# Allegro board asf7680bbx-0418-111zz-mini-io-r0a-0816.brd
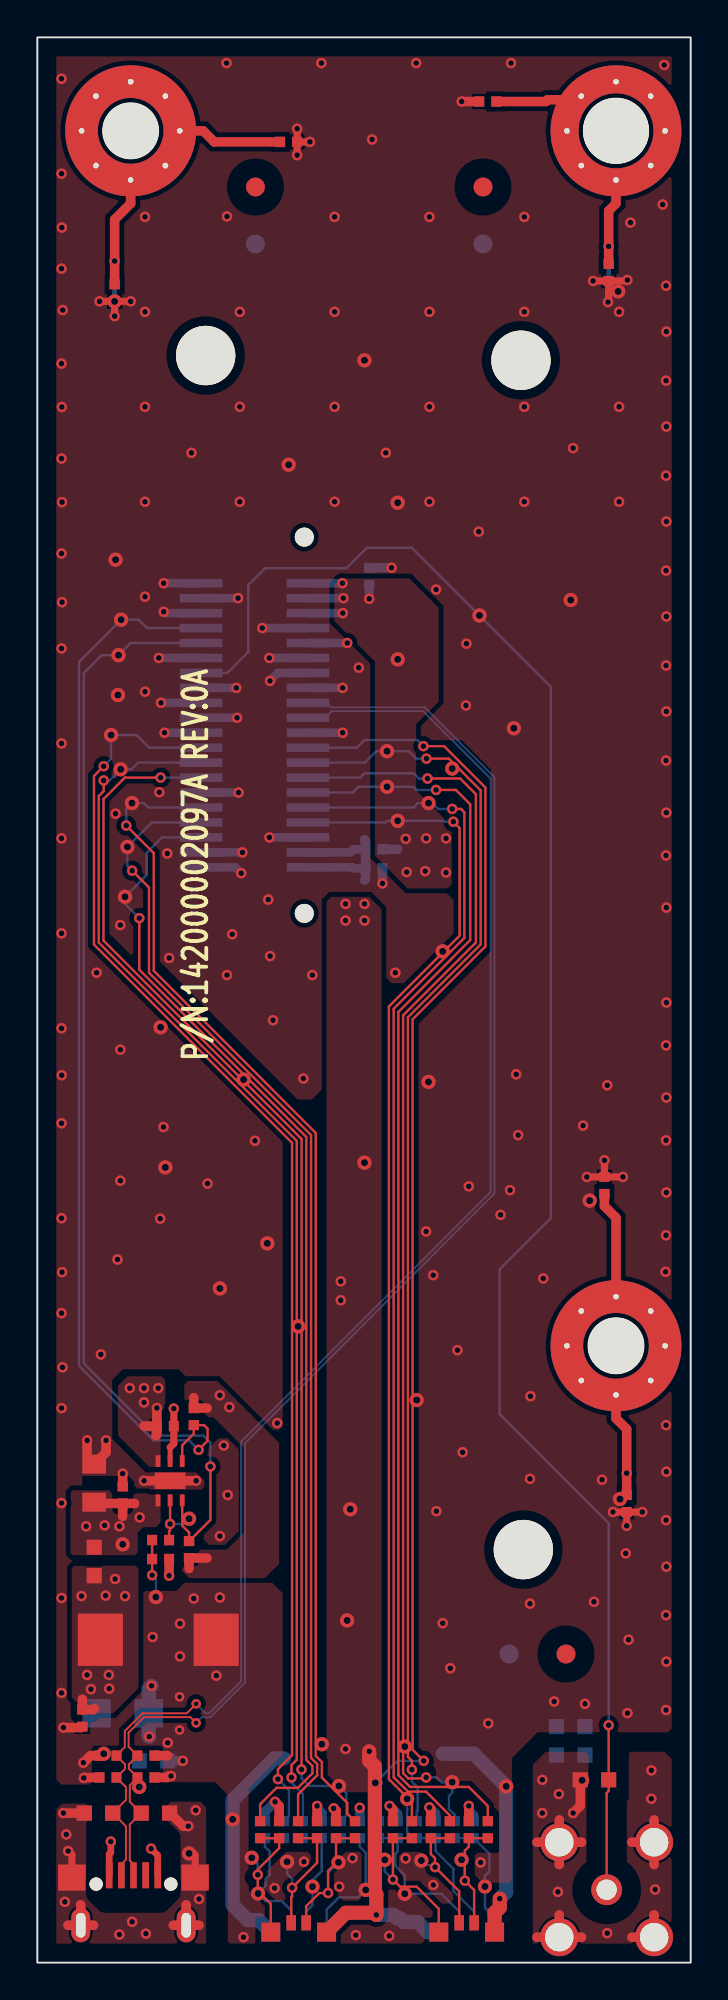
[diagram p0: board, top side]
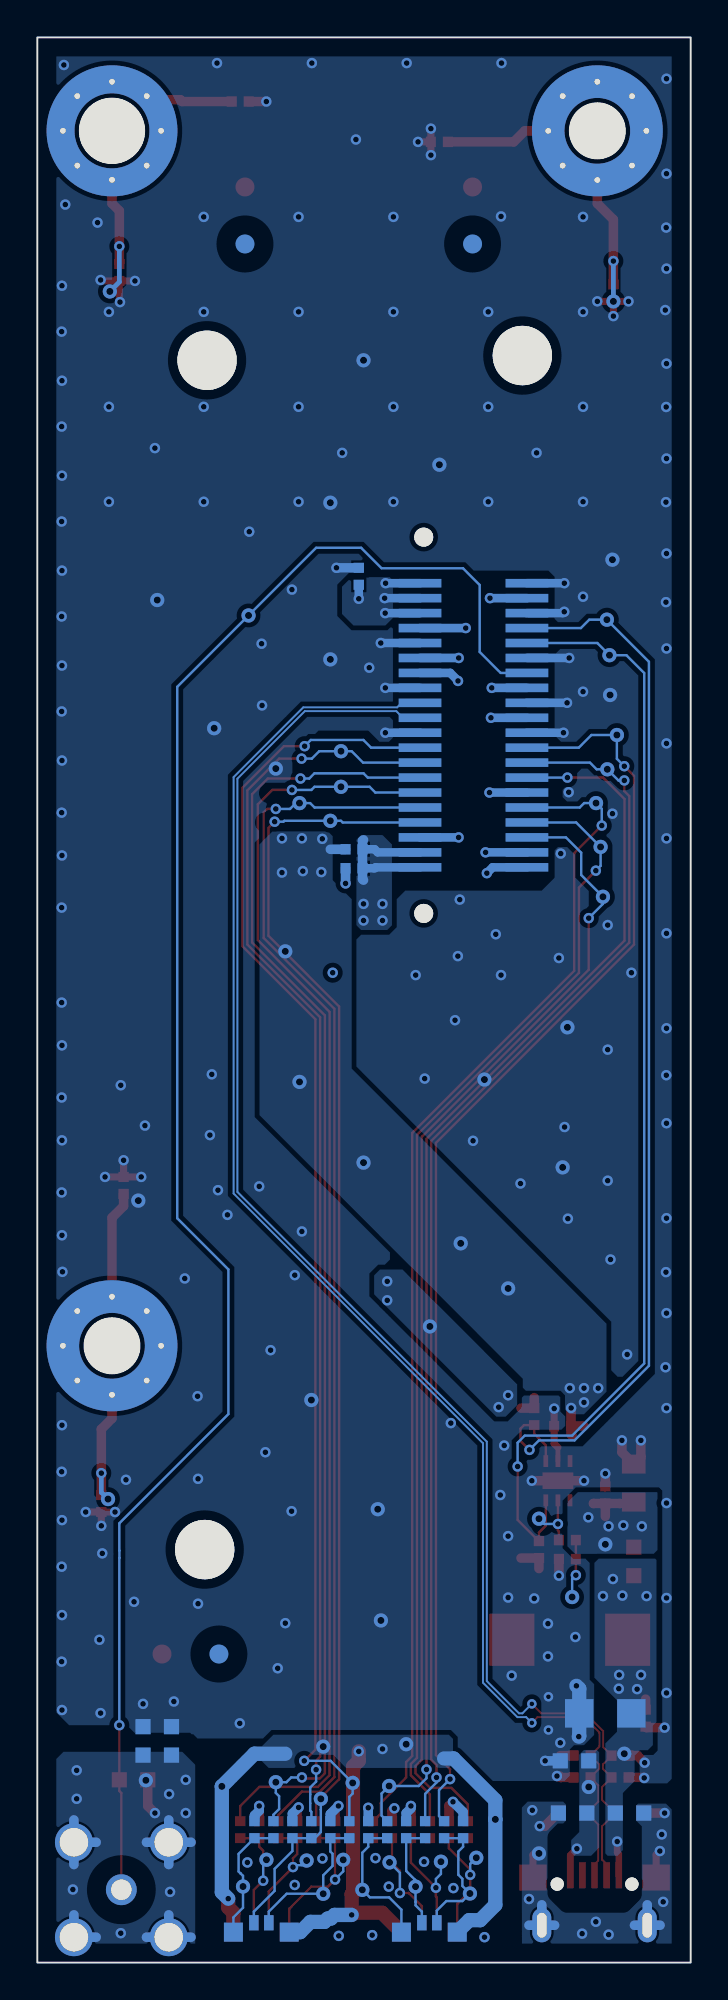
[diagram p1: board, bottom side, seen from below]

Outline 35 x 103 mm; copper layers: TOP, G2, V3, BOTTOM. Coordinates in mm from the lower left corner of the outline.
Outline path: rectangle 0,0 35,103

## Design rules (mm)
constraint set DEFAULT: min track width 0.127
net group BUS_USB: nets USB_DM USB_DP
net group BUS_GND: nets N24947217 N24947278 N24947339
net group CLS_MAC_1PPS_CON: nets MAC_1PPS_CON

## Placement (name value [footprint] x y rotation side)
C1  0.1uF  [CC0402]  24.13 99.57 90 top
C2  0.1uF  [CC0402]  13.46 97.41 270 top
C3  0.1uF  [CC0402]  30.61 90.42 180 top
C4  0.1uF  [CC0402]  4.14 89.33 180 top
C5  0.1uF  [CC0402]  30.38 41.58 0 top
C6  0.1uF/16V  [CC0402]  6.86 28.7 270 top
C7  10uF/16V  [CC0805]  3.05 25.65 180 top
C8  0.1uF/16V  [CC0402]  4.57 25.02 180 top
C9  0.1uF  [CC0402]  31.57 24.56 180 top
C10  100uF/6.3V  [CAP_6D2_2SP_4D3W7D3L2D1H]  6.48 17.27 0 top
C11  0.1uF/16V  [CC0402]  2.41 13.08 0 top
C12  47pF/50V  [CC0402]  3.78 9.91 270 top
C13  47pF/50V  [CC0402]  5.82 9.91 270 top
C14  0.1uF  [CC0402]  12.95 7.11 180 top
C15  0.1uF  [CC0402]  14.99 7.11 180 top
C16  0.1uF  [CC0402]  16 7.11 180 top
C17  0.1uF  [CC0402]  19.05 7.11 180 top
C18  0.1uF  [CC0402]  21.08 7.11 180 top
C19  0.1uF  [CC0402]  23.11 7.11 180 top
C20  0.1uF  [CC0402]  17.78 74.17 0 bottom
C21  0.1uF  [CC0402]  18.03 59.56 90 bottom
C22  0.1uF  [CC0402]  18.03 58.55 90 bottom
C23  22uF/16V  [CC1206]  4.57 13.34 270 bottom
C24  0.1uF  [CC0402]  12.19 7.11 0 bottom
C25  0.1uF  [CC0402]  15.24 7.11 0 bottom
C26  0.1uF  [CC0402]  17.27 7.11 0 bottom
C27  0.1uF  [CC0402]  19.3 7.11 0 bottom
C28  0.1uF  [CC0402]  21.34 7.11 0 bottom
C29  0.1uF  [CC0402]  23.37 7.11 0 bottom
CONN1  CU09S2M15BJ  [USB_D65_5SP_7D4W5L]  5.15 4.2 0 top
CONN2  BTB_MALE_SMD40  [CONNM_D8_20X2SP_3D251H_SAMTEC]  11.63 66.2 90 bottom
H1  *SCREW_8_2  [MTH_276C118D_8DP_OSP_6OCT]  5 98 0 top
H2  *SCREW_8_2  [MTH_276C138D_8DP_OSP_6OCT]  31 98 0 top
H3  *SCREW_8_2  [MTH_276C118D_8DP_OSP_6OCT]  31 33 0 top
L1  100MHz  [LC0603]  3.05 21.46 0 top
L2  ESD_1  [LC0603]  29.84 9.78 270 top
L3  ESD_1  [LC0603]  3.28 8 90 top
L4  ESD_1  [LC0603]  6.32 8 270 top
L5  100ohm/600mA  [LC0603]  29.34 11.86 180 bottom
L6  100MHz/5A/10mohm  [LC0603]  6.22 10.79 270 bottom
L7  ESD_1  [LC0603]  3.28 8 270 bottom
L8  ESD_1  [LC0603]  6.32 8 90 bottom
LED1  LED3_7  [LED_1D35_D8_4SP_3W2L_1]  14 1.63 180 top
LED2  LED3_7  [LED_1D35_D8_4SP_3W2L_1]  23 1.63 180 top
LED3  LED3_7  [LED_1D35_D8_4SP_3W2L_1]  14 1.63 0 bottom
LED4  LED3_7  [LED_1D35_D8_4SP_3W2L_1]  23 1.63 0 bottom
NOREF  -  []  8.51 13.34 0 top
NOREF#2  -  []  -21.21 -39.78 0 top
NOREF#3  -  [unnamed#2]  26.04 22.1 0 top
NOREF#4  -  [unnamed#2]  23.88 95 0 top
NOREF#5  -  []  0 0 0 top
NOREF#6  -  [unnamed#2]  25.91 85.72 0 top
NOREF#7  -  []  33.35 48.59 90 top
NOREF#8  -  [unnamed#2]  28.32 16.51 0 top
NOREF#9  -  []  224.94 -67.67 0 top
NOREF#10  -  [unnamed#2]  11.68 95 0 top
NOREF#11  -  [unnamed#2]  9.02 85.98 0 top
NOREF#12  -  [unnamed#2]  25.27 16.51 180 bottom
NOREF#13  -  [unnamed#2]  23.88 91.95 180 bottom
NOREF#14  -  [unnamed#2]  11.68 91.95 180 bottom
R1  100Kohm  [RC0402]  8.38 29.21 180 top
R2  12.7Kohm  [RC0402]  6.6 22.61 90 top
R3  100Kohm  [RC0402]  8.13 22.1 0 top
R4  12.7Kohm  [RC0402]  6.6 21.59 270 top
R5  15Kohm  [RC0402]  3.78 11.07 90 top
R6  15Kohm  [RC0402]  5.82 11.07 90 top
R7  150ohm  [RC0402]  11.94 7.11 0 top
R8  150ohm  [RC0402]  13.97 7.11 0 top
R9  220ohm  [RC0402]  17.02 7.11 0 top
R10  150ohm  [RC0402]  20.07 7.11 0 top
R11  150ohm  [RC0402]  22.1 7.11 0 top
R12  220ohm  [RC0402]  24.13 7.11 0 top
R13  0ohm  [RC0603]  27.81 11.86 0 bottom
R14  220ohm  [RC0402]  13.21 7.11 180 bottom
R15  150ohm  [RC0402]  14.22 7.11 180 bottom
R16  150ohm  [RC0402]  16.26 7.11 180 bottom
R17  220ohm  [RC0402]  18.29 7.11 180 bottom
R18  150ohm  [RC0402]  20.32 7.11 180 bottom
R19  150ohm  [RC0402]  22.35 7.11 180 bottom
SW1  M01-064011-00  [CONN_5D08_5DP_7W14L_PIP]  30.5 3.9 0 top
U1  TPS2553DRVR  [QFN_D65X2D1_6SP_2WLD8H]  7.11 25.78 0 top

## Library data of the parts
C1-C9 C11-C29 = C_NP
C10 = C_P
CONN1 = CONN_USB_FEMALE_5P_G4
CONN2 = BTB_MALE_SMD40
H1-H3 = SCREW_8_1
L1 L5 = BEAD
L2-L4 L7 L8 = ESD_1
L6 = BEAD: room: 8
LED1-LED4 = LED3_7
R1-R4 R7-R19 = R: tolerance: 1%
R5 R6 = R
SW1 = CONN_RF_MALE_DIP5_G4
U1 = MONITOR_CUR_TI_TPS2553

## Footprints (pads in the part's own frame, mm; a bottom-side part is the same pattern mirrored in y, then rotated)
CAP_6D2_2SP_4D3W7D3L2D1H
  rect 2.413x2.794 smd: A(-3.1,0) C(3.1,0)
CC0402
  rect 0.559x0.539 smd: 1(0,0.454) 2(0,-0.454)
CC0805
  rect 1.27x1.016 smd: 1(0,1.016) 2(0,-1.016)
CC1206
  rect 1.524x1.524 smd: 1(0,1.397) 2(0,-1.397)
CONN_5D08_5DP_7W14L_PIP
  round 1.651 hole 1.092: 1(0,0)
  round 2.032 hole 1.524: G1(-2.54,-2.54) G2(2.54,-2.54) G3(2.54,2.54) G4(-2.54,2.54)
CONNM_D8_20X2SP_3D251H_SAMTEC
  round 1.016 hole 1.016 unplated: (-10.065,2.666) (10.065,2.666)
  rect 0.457x2.286 smd: 1(-7.6,-2.864) 2(-7.6,2.864) 3(-6.8,-2.864) 4(-6.8,2.864) 5(-6,-2.864) 6(-6,2.864) 7(-5.2,-2.864) 8(-5.2,2.864) 9(-4.4,-2.864) 10(-4.4,2.864) 11(-3.6,-2.864) 12(-3.6,2.864) 13(-2.8,-2.864) 14(-2.8,2.864) 15(-2,-2.864) 16(-2,2.864) 17(-1.2,-2.864) 18(-1.2,2.864) 19(-0.4,-2.864) 20(-0.4,2.864) 21(0.4,-2.864) 22(0.4,2.864) 23(1.2,-2.864) 24(1.2,2.864) 25(2,-2.864) 26(2,2.864) 27(2.8,-2.864) 28(2.8,2.864) 29(3.6,-2.864) 30(3.6,2.864) 31(4.4,-2.864) 32(4.4,2.864) 33(5.2,-2.864) 34(5.2,2.864) 35(6,-2.864) 36(6,2.864) 37(6.8,-2.864) 38(6.8,2.864) 39(7.6,-2.864) 40(7.6,2.864)
LC0603
  rect 0.813x0.813 smd: 1(0,0.762) 2(0,-0.762)
LED_1D35_D8_4SP_3W2L_1
  rect 1.016x1.016 smd: A(-1.496,0) C3(1.496,0)
  rect 0.508x0.813 smd: C1(-0.4,-0.5) C2(0.4,-0.5)
MTH_276C118D_8DP_OSP_6OCT
  round 2.997 hole 2.997 unplated: (0,0)
  round 0.889 hole 0.305: 1(0,2.629) 2(1.859,1.859) 3(2.629,0) 4(1.859,-1.859) 5(0,-2.629) 6(-1.859,-1.859) 7(-2.629,0) 8(-1.859,1.859)
MTH_276C138D_8DP_OSP_6OCT
  round 3.505 hole 3.505 unplated: (0,0)
  round 0.889 hole 0.305: 1(0,2.629) 2(1.859,1.859) 3(2.629,0) 4(1.859,-1.859) 5(0,-2.629) 6(-1.859,-1.859) 7(-2.629,0) 8(-1.859,1.859)
QFN_D65X2D1_6SP_2WLD8H
  rect 0.254x0.635 smd: 1(-0.65,-1.05) 2(0,-1.05) 3(0.65,-1.05) 4(0.65,1.05) 5(0,1.05) 6(-0.65,1.05)
  rect 1.651x0.889 smd: G1(0,0)
RC0402
  rect 0.559x0.539 smd: 1(0,0.454) 2(0,-0.454)
RC0603
  rect 0.813x0.813 smd: 1(0,0.762) 2(0,-0.762)
unnamed#2
  round 3.175 hole 3.175 unplated: (0,0)
USB_D65_5SP_7D4W5L
  round 0.711 hole 0.711 unplated: (-2,0) (2,0)
  rect 0.356x1.397 smd: 1(-1.3,0.475) 2(-0.65,0.475) 3(0,0.475) 4(0.65,0.475) 5(1.3,0.475)
  rect 1.473x1.397 smd: G1(-3.3,0.35) G2(3.3,0.35)
  oval 1.016x1.829 hole 0.508x1.321: G3(-2.825,-2.2) G4(2.825,-2.2)

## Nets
GND: C1.1 C2.1 C3.1 C4.1 C5.1 C6.1 C7.2 C8.2 C9.1 C10.C C11.2 C12.2 C13.1 C14.2 C15.2 C16.2 C17.2 C18.2 C19.2 C20.2 C22.1 C23.2 C24.2 C25.2 C26.2 C27.2 C28.2 C29.2 CONN2.1 CONN2.3 CONN2.6 CONN2.11 CONN2.19 CONN2.20 CONN2.21 CONN2.23 CONN2.25 CONN2.26 CONN2.28 CONN2.29 CONN2.30 CONN2.32 CONN2.34 CONN2.35 CONN2.37 CONN2.39 L5.1 L6.2 R4.1 R5.1 R6.2 R13.2 U1.5(GND) U1.G1(G_PAD)
GND_USB: CONN1.5(GND) L6.1 L8.2
VBUS_5V: C10.A C11.1 C23.1 CONN1.1(VBUS) L1.2 L7.2
CHASSIS: CONN1.G1 CONN1.G2 CONN1.G3 CONN1.G4 L3.1 L4.1 L7.1 L8.1
CHASSIS_1: L2.2 L5.2 R13.1 SW1.G1 SW1.G2 SW1.G3 SW1.G4
DIAG_B_R: C26.1 LED3.C3 R16.2
DIAG_G_R: C25.1 LED3.C2 R15.2
DIAG_LED_B: CONN2.13 R16.1
DIAG_LED_G: CONN2.15 R15.1
DIAG_LED_R: CONN2.17 R14.1
DIAG_R_R: C24.1 LED3.C1 R14.2
FAN_B_R: C29.1 LED4.C3 R19.2
FAN_G_R: C28.1 LED4.C2 R18.2
FAN_LED_B: CONN2.14 R19.1
FAN_LED_G: CONN2.16 R18.1
FAN_LED_R: CONN2.18 R17.1
FAN_R_R: C27.1 LED4.C1 R17.2
LOC_B_R: C14.1 LED1.C3 R7.2
LOC_G_R: C15.1 LED1.C2 R8.2
LOC_LED_B: CONN2.5 R7.1
LOC_LED_G: CONN2.7 R8.1
LOC_LED_R: CONN2.9 R9.1
LOC_R_R: C16.1 LED1.C1 R9.2
MAC_1PPS_CON: CONN2.27 L2.1 SW1.1
PWR_LED_B: CONN2.8 R10.1
PWR_LED_G: CONN2.10 R11.1
PWR_LED_R: CONN2.12 R12.1
SYSTEM_B_R: C17.1 LED2.C3 R10.2
SYSTEM_G_R: C18.1 LED2.C2 R11.2
SYSTEM_R_R: C19.1 LED2.C1 R12.2
USB_DM: C12.1 CONN1.2(D-) CONN2.22 L3.2 R5.2
USB_DP: C13.2 CONN1.3(D+) CONN2.24 L4.2 R6.1
USB_ILIM: R2.2 U1.2(ILIM)
USB_ILIM_R: R2.1 R4.2
USB_PWR_FAULT_N: CONN2.31 R3.1 U1.3(F\A\U\L\T\)
USB_PWR_ON: CONN2.33 R1.1 U1.4(EN)
USB_VBUS: C7.1 C8.1 L1.1 U1.1(OUT)
USB_VCC5P0: C6.2 C20.1 C21.1 CONN2.36 CONN2.38 CONN2.40 U1.6(IN)
VSTB_3V3: C21.2 C22.2 CONN2.2 CONN2.4 LED1.A LED2.A LED3.A LED4.A R1.2 R3.2
N24947217: C2.2 C4.2 H1.1 H1.2 H1.3 H1.4 H1.5 H1.6 H1.7 H1.8
N24947278: C5.2 C9.2 H3.1 H3.2 H3.3 H3.4 H3.5 H3.6 H3.7 H3.8
N24947339: C1.2 C3.2 H2.1 H2.2 H2.3 H2.4 H2.5 H2.6 H2.7 H2.8

Pads without a net: CONN1 4

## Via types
v1: diameter 0.762, hole 0.381, TOP to BOTTOM, 63 vias
v2: diameter 0.559, hole 0.305, TOP to BOTTOM, 313 vias
v3: diameter 0.508, hole 0.254, TOP to BOTTOM, 4 vias

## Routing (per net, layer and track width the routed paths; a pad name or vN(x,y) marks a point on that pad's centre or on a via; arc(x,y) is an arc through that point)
GND: length 82.2
  TOP w0.254: 7.11,27.57 U1.5
  TOP w0.381: v2(7.31,29.64) C6.1 7.31,27.77 7.11,27.57 ; C2.1 v2(13.92,98.12) ; C2.1 v2(13.92,96.7) ; C2.1 v2(14.61,97.41) ; C4.1 v2(3.33,88.88) ; C4.1 v2(5,88.88) ; C4.1 v2(4.14,88.09) ; v2(30.57,88.84) 30.61,88.87 C3.1 ; C9.1 v2(31.57,23.37) ; C9.1 v2(32.41,24.11) ; C9.1 v2(30.84,24.11) ; C5.1 v2(29.44,42.03) ; C5.1 v2(31.37,42.03) ; C5.1 v2(30.38,42.93) ; C3.1 31.52,89.97 31.57,90.02 v2(31.61,90.02) ; C3.1 v2(29.77,89.97)
  TOP w0.508: v2(3.68,27.94) 3.68,27.3 C7.2 2.67,27.05 v2(2.67,27.94) ; C1.1 v2(22.73,99.57) ; v2(5.71,25.78) U1.G1 v2(8.51,25.78) ; C13.1 6.96,9.91 7.04,9.98 v2(7.16,9.98) ; v2(14.99,8.38) 14.99,8.38 C15.2 ; v2(18.87,8.38) 19.05,8.2 C17.2 ; C11.2 2.36,12.57 v2(1.4,12.57) ; C8.2 v2(4.57,26.16) ; C14.2 12.95,8.38 v2(12.73,8.6) ; v2(21,8.3) 21.08,8.23 C18.2 ; C16.2 16,8.13 v2(15.87,8.25) ; R6.2 6.99,11.07 ; C19.2 v2(23.11,8.38) ; R4.1 v2(7.06,20.7) ; v2(2.46,10.69) 2.84,11.07 R5.1 ; v2(2.49,9.88) 2.51,9.91 C12.2
  BOTTOM w0.457: CONN2.34 v2(12.05,71.4) ; CONN2.29 v2(6.51,69.8) ; v2(6.77,72.27) 6.84,72.2 CONN2.35 ; CONN2.28 12.88,69 12.46,68.58 v2(12.46,68.57) ; CONN2.21 v2(10.7,66.6) ; CONN2.6 v2(12.43,60.2) ; CONN2.25 v2(10.66,68.2) ; CONN2.20 v2(16.36,65.8) ; CONN2.1 10.61,58.6 v2(10.92,58.29) ; CONN2.37 v2(10.75,73) ; CONN2.32 v2(16.6,70.6) ; CONN2.23 v2(6.62,67.4) ; CONN2.30 v2(12.43,69.8) ; CONN2.26 v2(16.36,68.2) ; CONN2.19 v2(6.81,65.8) ; CONN2.3 v2(10.99,59.4) ; CONN2.39 v2(6.77,73.8) ; CONN2.11 v2(10.78,62.6)
  BOTTOM w0.508: C26.2 v2(17.27,8.28) ; C28.2 21.34,7.97 v2(21,8.3) ; v2(12.73,8.6) 12.19,8.06 C24.2 ; v2(14.99,8.38) 14.99,8.25 15.24,8 C25.2 ; v2(23.11,8.38) 23.11,8.13 23.37,7.87 C29.2 ; C20.2 v2(18.98,74.62) ; L6.2 v2(7.8,10.79) ; C22.1 v2(18.49,57.74) ; C27.2 19.3,7.95 v2(18.87,8.38)
  BOTTOM w0.762: v2(6.12,14.81) 5.97,14.66 C23.2 5.97,12.12 v2(5.99,12.09)
  vias: v1(4.19,75.06) v1(4.32,67.82) v1(6.6,50.04) v1(6.86,42.55) v1(11.05,47.24) v1(13.46,80.14) v1(16.59,18.31) v1(16.76,24.26) v1(17.53,85.72) v1(19.3,78.11) v1(19.3,69.72) v1(20.32,30.1) v1(22.23,63.88) v1(25.53,66.04) v1(28.57,72.9) v1(29.59,40.77) v2(1.3,100.79) v2(1.3,95.71) v2(1.31,92.82) v2(1.3,90.63) v2(1.3,85.55) v2(1.31,83.23) v2(1.3,80.47) v2(1.32,78.14) v2(1.3,75.39) v2(1.32,72.78) v2(1.3,70.31) v2(1.3,65.23) v2(1.3,60.15) v2(1.3,55.07) v2(1.3,49.99) v2(1.31,47.48) v2(1.3,44.91) v2(1.3,39.83) v2(1.32,36.94) v2(1.3,34.75) v2(1.35,31.85) v2(1.3,29.67) v2(1.3,24.59) v2(1.3,19.51) v2(1.3,14.43) v2(1.36,88.41) v2(3.17,52.96) v2(3.4,32.54) v2(4.19,61.47) v2(4.29,37.62) v2(4.45,55.51) v2(4.45,48.84) v2(4.45,41.83) v2(5.77,93.4) v2(5.77,88.32) v2(5.77,83.24) v2(5.77,78.16) v2(5.77,73.08) v2(5.77,68) v2(6.18,17.42) v2(6.53,62.62) v2(6.58,39.8) v2(6.76,44.7) v2(6.96,59.33) v2(6.99,11.76) v2(7.06,53.75) v2(7.65,18.14) v2(7.65,16.38) v2(8.26,80.77) v2(8.38,19.48) v2(9.12,41.68) v2(9.59,15.35) v2(9.78,22.82) v2(9.78,19.53) v2(9.99,27.67) v2(10.13,101.63) v2(10.16,93.42) v2(10.16,52.83) v2(10.2,25.02) v2(10.44,55.02) v2(10.85,88.32) v2(10.85,83.24) v2(10.85,78.16) v2(11.04,1.36) v2(11.66,43.97) v2(12.37,56.87) v2(12.47,53.85) v2(12.62,50.42) v2(12.71,3.99) v2(12.85,28.86) v2(14.25,47.29) v2(14.28,5.4) v2(14.73,52.83) v2(15.21,101.63) v2(15.93,93.4) v2(15.93,88.32) v2(15.93,83.24) v2(15.93,78.16) v2(16.17,4.07) v2(16.89,5.59) v2(17.06,1.47) v2(17.22,69.28) v2(17.93,97.54) v2(18.67,80.77) v2(18.85,1.43) v2(19.18,52.96) v2(19.73,5.57) v2(20.29,101.63) v2(20.83,39.12) v2(21.01,93.4) v2(21.01,88.32) v2(21.01,83.24) v2(21.01,78.16) v2(21.21,36.78) v2(21.21,4.15) v2(21.36,73.46) v2(21.38,24.15) v2(21.72,18.16) v2(22.12,15.75) v2(22.5,32.77) v2(22.78,27.3) v2(22.99,70.56) v2(22.96,67.26) v2(23.11,41.53) v2(23.65,76.56) v2(23.75,5.36) v2(24.16,12.8) v2(24.82,40.01) v2(25.32,41.33) v2(25.37,101.63) v2(25.65,47.52) v2(25.76,44.27) v2(26.09,93.4) v2(26.09,88.32) v2(26.09,83.24) v2(26.09,78.16) v2(26.42,30.3) v2(26.39,25.88) v2(26.39,19.2) v2(27.1,36.6) v2(27.69,13.97) v2(28.7,81.03) v2(29.24,44.78) v2(29.34,13.84) v2(29.82,19.3) v2(30.25,25.83) v2(30.53,46.94) v2(31.17,88.32) v2(31.17,83.24) v2(31.17,78.16) v2(31.52,21.89) v2(31.61,13.35) v2(31.67,17.27) v2(31.78,93.09) v2(33.5,94.06) v2(33.58,101.52) v2(33.68,89.71) v2(33.7,87.26) v2(33.68,84.63) v2(33.7,82.18) v2(33.68,79.55) v2(33.7,77.1) v2(33.68,74.47) v2(33.7,72.02) v2(33.68,69.39) v2(33.7,66.94) v2(33.68,64.31) v2(33.7,61.52) v2(33.68,59.23) v2(33.7,56.44) v2(33.7,51.36) v2(33.68,49.07) v2(33.7,46.28) v2(33.68,43.99) v2(33.7,41.2) v2(33.68,38.91) v2(33.66,36.96) v2(33.68,28.75) v2(33.7,26.26) v2(33.68,23.67) v2(33.7,21.18) v2(33.68,18.59) v2(33.7,16.1) v2(33.68,13.51) v3(7.62,14.22) v3(7.62,12.45)
GND_USB: length 1.6
  TOP w0.356: CONN1.5 6.45,5.74 v2(6.1,6.1)
  vias: v1(5.46,9.4)
VBUS_5V: length 3.1
  TOP w0.356: CONN1.1 3.85,5.81 3.94,5.89 v2(3.94,6.48)
  TOP w0.508: 2.41,14.1 C11.1 2.99,13.54 3.05,13.59
  vias: v1(3.56,11.18) v2(2.36,19.61) v2(2.66,15.39) v2(2.87,14.63) v2(3.66,19.63) v2(3.83,15.39) v2(3.85,14.66) v2(4.17,20.52) v2(4.7,19.61)
CHASSIS: length 25
  TOP w0.381: 8.33,5.85 8.33,5.85 8.36,5.85 8.45,5.76 CONN1.G2 ; CONN1.G1 1.85,5.77 v2(1.65,5.97)
  TOP w0.508: CONN1.G3 3.01,2 ; CONN1.G3 2.33,3.09 ; CONN1.G3 1.64,2 ; CONN1.G4 8.66,2 ; CONN1.G4 7.29,2 ; CONN1.G4 7.98,3.09 ; L4.1 7.11,8 7.81,7.3 v2(8.09,7.3) ; L3.1 v2(1.4,8)
  G2 w0.508: 1.64,2 CONN1.G3 ; CONN1.G3 3.01,2 ; CONN1.G3 2.33,3.09 ; 7.29,2 CONN1.G4 ; CONN1.G4 7.98,3.09 ; CONN1.G4 8.66,2
  V3 w0.508: CONN1.G4 7.98,3.09 ; CONN1.G4 7.29,2 ; CONN1.G4 8.66,2 ; CONN1.G3 2.33,3.09 ; CONN1.G3 1.64,2 ; CONN1.G3 3.01,2
  BOTTOM w0.508: 1.64,2 CONN1.G3 ; CONN1.G3 3.01,2 ; CONN1.G3 2.33,3.09 ; 7.29,2 CONN1.G4 ; CONN1.G4 8.66,2 ; CONN1.G4 7.98,3.09
  vias: v1(8.13,5.84) v2(1.55,6.86) v2(1.47,3.25) v2(4.39,1.5) v2(5.08,2.18) v2(5.82,1.55) v2(8.48,8.15) v2(8.66,3.4)
CHASSIS_1: length 56.9
  TOP w0.508: SW1.G3 33.04,7.63 ; SW1.G3 31.85,6.44 ; SW1.G3 33.04,5.25 ; 26.77,1.36 SW1.G1 ; SW1.G1 29.15,1.36 ; SW1.G1 27.96,2.55 ; SW1.G4 29.15,6.44 ; SW1.G4 27.96,5.25 ; SW1.G4 26.77,6.44 ; SW1.G4 27.96,7.63 ; 31.85,1.36 SW1.G2 33.04,2.55 ; L2.2 29.08,8.38 v2(28.7,8)
  G2 w0.508: 27.96,5.25 SW1.G4 ; SW1.G4 26.77,6.44 ; SW1.G4 27.96,7.63 ; SW1.G4 29.15,6.44 ; 27.96,2.55 SW1.G1 29.15,1.36 ; SW1.G3 33.04,7.63 ; SW1.G3 31.85,6.44 ; SW1.G3 33.04,5.25 ; 33.04,2.55 SW1.G2 31.85,1.36
  V3 w0.508: 31.85,1.36 SW1.G2 33.04,2.55 ; 27.96,5.25 SW1.G4 ; SW1.G4 29.15,6.44 ; SW1.G4 26.77,6.44 ; SW1.G4 27.96,7.63 ; 27.96,2.55 SW1.G1 29.15,1.36 ; 33.04,5.25 SW1.G3 ; SW1.G3 33.04,7.63 ; SW1.G3 31.85,6.44
  BOTTOM w0.508: 27.96,5.25 SW1.G4 ; SW1.G4 26.77,6.44 ; SW1.G4 29.15,6.44 ; SW1.G4 27.96,7.63 ; 31.85,6.44 SW1.G3 ; SW1.G3 33.04,5.25 ; SW1.G3 33.04,7.63 ; 33.04,2.55 SW1.G2 31.85,1.36 ; SW1.G1 29.15,1.36 ; SW1.G1 26.77,1.36 ; SW1.G1 27.96,2.55
  vias: v1(29.18,9.75) v2(27.05,9.78) v2(27.05,8) v2(27.94,9.02) v2(27.89,3.78) v2(30.53,1.57) v2(32.89,10.29) v2(32.89,8.76) v2(33.1,3.91)
DIAG_B_R: length 7.6
  BOTTOM w0.127: LED3.C3 15.5,2.83 16.15,3.49 17.19,3.49 v1(17.59,3.89) 17.59,5.88 17.27,6.2 C26.1 R16.2
DIAG_G_R: length 5.9
  BOTTOM w0.127: LED3.C2 14.4,2.73 14.74,3.07 14.74,3.25 14.74,3.25 v1(14.74,4.06) 14.74,4.4 14.8,4.45 14.8,4.46 15.24,4.91 C25.1 R15.2
DIAG_LED_B: length 66.8
  TOP w0.127: v2(14.15,10.33) 14.15,44.07 3.54,54.68 3.54,62.25 4.69,63.4 v2(6.6,63.4)
  BOTTOM w0.127: v2(6.6,63.4) CONN2.13 ; v2(14.15,10.33) 14.15,9.86 14.57,9.45 v1(16.15,9.45) 16.56,9.04 16.56,7.87 R16.1
DIAG_LED_G: length 66.2
  TOP w0.127: v2(13.62,9.91) 13.62,10.57 13.9,10.86 13.9,43.96 3.29,54.57 3.29,62.41 3.56,62.68 v2(3.56,63.25)
  BOTTOM w0.127: R15.1 14.22,9.03 13.62,9.63 v2(13.62,9.91) ; CONN2.15 5.39,64.2 5.04,63.84 v1(4.47,63.84) 3.87,63.25 v2(3.56,63.25)
DIAG_LED_R: length 68.7
  TOP w0.127: v2(12.89,9.82) 12.89,10.35 13.65,11.11 13.65,43.86 3.04,54.47 3.04,63.49 v2(3.56,64.01)
  BOTTOM w0.127: v2(12.89,9.82) 13.48,9.23 13.48,7.84 R14.1 ; v2(3.56,64.01) 3.95,64.4 v1(3.95,65.68) 5.32,65.68 5.99,65 CONN2.17
DIAG_R_R: length 7.1
  BOTTOM w0.127: LED3.C1 13.6,2.78 13.09,3.29 12.23,3.29 v1(11.82,3.7) 12.23,4.1 12.23,4.48 12.45,4.7 12.45,5.94 12.19,6.2 C24.1 R14.2
FAN_B_R: length 6.7
  BOTTOM w0.127: R19.2 C29.1 23.38,6.66 24.22,5.82 24.22,4.88 24.12,4.78 24.12,4.78 23.98,4.64 v1(23.98,4.07) 23.98,2.93 24.5,2.42 LED4.C3
FAN_G_R: length 8.8
  BOTTOM w0.127: LED4.C2 23.4,2.73 22.29,3.84 22.29,5.02 21.34,5.97 C28.1 R18.2 20.14,6.66 19.81,6.98 19.81,8.19 v1(19.81,8.76)
FAN_LED_B: length 68.7
  TOP w0.127: v2(20.83,9.91) 20.78,9.86 19.87,9.86 19.6,10.13 19.6,50.68 23.5,54.58 23.5,62.51 22.66,63.35 v2(20.9,63.35)
  BOTTOM w0.127: v2(20.83,9.91) 21.4,9.91 21.65,9.65 v1(22.23,9.65) 22.23,9.08 22.05,8.9 22.05,8.22 22.35,7.91 R19.1 ; CONN2.14 17.3,63.4 17.53,63.63 20.15,63.63 20.43,63.35 v2(20.9,63.35)
FAN_LED_G: length 67.4
  TOP w0.127: v2(20.85,64.41) 22.05,64.41 23.75,62.71 23.75,54.47 19.85,50.57 19.85,11.01 20.07,10.79 v2(20.07,10.33)
  BOTTOM w0.127: v2(20.07,10.33) 20.07,9.68 20.38,9.37 20.38,9 20.38,9 20.38,8.53 20.38,8.52 20.38,8.13 20.32,8.07 R18.1 ; CONN2.16 17.55,64.2 18.16,64.81 v1(18.73,64.81) 19.9,64.81 20.3,64.41 v2(20.85,64.41)
FAN_LED_R: length 69.9
  TOP w0.127: v2(20.7,10.79) 20.1,11.39 20.1,50.47 24,54.37 24,62.87 21.79,65.08 v2(20.68,65.08)
  BOTTOM w0.127: R17.1 18.29,8.86 18.11,9.04 v1(18.11,9.62) 19.29,10.79 v2(20.7,10.79) ; v2(20.68,65.08) 20.35,65.41 17.53,65.41 17.12,65 CONN2.18
FAN_R_R: length 8.2
  BOTTOM w0.127: LED4.C1 22.6,2.73 21.64,3.68 v1(19.68,3.68) 19.68,4.67 19.18,5.17 19.18,5.82 19.3,5.94 C27.1 R17.2
LOC_B_R: length 7.8
  TOP w0.127: R7.2 C14.1 12.95,6.12 11.81,4.98 v2(11.81,4.7) 11.81,3.84 12.5,3.14 LED1.C3
  BOTTOM w0.127: v2(11.81,4.7) 11.81,5.28 v1(11.48,5.61)
LOC_G_R: length 7.6
  TOP w0.127: LED1.C2 13.6,3.49 13.65,3.54 v2(13.65,4.01) 14.99,5.34 C15.1 R8.2
  BOTTOM w0.127: v2(13.65,4.01) 13.65,4.48 13.38,4.74 v1(13.38,5.4)
LOC_LED_B: length 61.5
  TOP w0.127: v2(5.46,55.88) 5.46,53.12 14.41,44.17 14.41,10.85 14.74,10.52 14.74,10.13 13.96,9.35 12.82,9.35 11.94,8.47 R7.1
  BOTTOM w0.127: v2(5.46,55.88) 4.7,56.64 v1(4.7,57.02) 5.87,58.19 5.87,59.38 6.68,60.2 CONN2.5
LOC_LED_G: length 61.2
  TOP w0.127: v2(5.08,58.42) 5.98,57.52 5.98,52.96 14.66,44.28 14.66,10.95 14.99,10.62 14.99,10.02 13.97,9 R8.1
  BOTTOM w0.127: CONN2.7 6.13,61 v1(4.83,59.69) 4.83,58.67 v2(5.08,58.42)
LOC_LED_R: length 63.5
  TOP w0.127: v2(4.76,60.83) 6.24,59.36 6.24,53.06 14.92,44.38 14.92,11.06 15.24,10.73 15.24,9.9 16.6,8.54 16.6,7.97 17.01,7.57 R9.1
  BOTTOM w0.127: v2(4.76,60.83) 4.76,61.73 v1(5.07,62.04) 5.71,62.04 5.94,61.8 CONN2.9
LOC_R_R: length 8.4
  TOP w0.127: R9.2 C16.1 16,5.33 15.58,4.91 v2(15.58,3.72) 15.11,3.72 14.4,3.02 LED1.C1
  BOTTOM w0.127: v2(15.58,3.72) 15.58,4.81 v1(16.13,5.36)
MAC_1PPS_CON: length 94.6
  TOP w0.127: SW1.1 30.5,9.08 30.61,9.18 L2.1 v2(30.61,12.7)
  BOTTOM w0.127: v2(30.61,12.7) 30.61,21.65 30.6,21.65 30.6,22.04 30.61,22.05 30.61,23.5 24.77,29.35 24.77,37.08 27.51,39.83 27.51,68.25 v1(23.69,72.07) 20.07,75.69 17.65,75.69 16.56,74.6 12.2,74.6 11.3,73.71 11.3,70.12 10.18,69 CONN2.27
PWR_LED_B: length 63.5
  TOP w0.127: v2(22.29,61.04) 22.62,60.71 22.62,54.94 18.83,51.15 18.83,9.81 20.07,8.58 R10.1
  BOTTOM w0.127: CONN2.8 18.64,61 18.73,61.09 v1(19.3,61.09) 21.77,61.09 21.82,61.04 v2(22.29,61.04)
PWR_LED_G: length 66
  TOP w0.127: R11.1 22.1,7.87 20.83,9.14 19.86,9.14 19.09,9.92 19.09,51.03 22.87,54.82 22.87,61.54 22.69,61.72 v2(22.23,61.72)
  BOTTOM w0.127: CONN2.10 20.15,61.8 20.39,62.03 v1(20.96,62.03) 21.15,62.03 21.46,61.72 v2(22.23,61.72)
PWR_LED_R: length 69
  TOP w0.127: v2(21.36,62.74) 22.42,62.74 23.19,61.97 23.19,54.71 19.34,50.86 19.34,10.02 19.97,9.4 23.11,9.4 24.13,8.38 R12.1
  BOTTOM w0.127: v2(21.36,62.74) 20.32,62.74 20.15,62.91 v1(18.74,62.91) 17.2,62.91 16.89,62.6 CONN2.12
SYSTEM_B_R: length 8.8
  TOP w0.127: R10.2 C17.1 v2(19.05,4.45) 19.43,4.06 20.32,4.06 21.5,2.88 LED2.C3
  BOTTOM w0.127: v2(19.05,4.45) 18.61,4.88 v1(18.61,5.5)
SYSTEM_G_R: length 7
  TOP w0.127: R11.2 C18.1 21.08,5.8 21.3,5.58 v2(21.3,5.11) 22.6,3.82 LED2.C2
  BOTTOM w0.127: v2(21.3,5.11) 21.2,5.21 20.82,5.21 v1(20.57,5.46)
SYSTEM_R_R: length 7
  TOP w0.127: LED2.C1 23.4,3.88 v2(22.9,4.38) 22.9,5.99 23.11,6.2 C19.1 R12.2
  BOTTOM w0.127: v1(22.73,5.5) 22.9,5.33 v2(22.9,4.38)
USB_DM: length 82.2
  TOP w0.102: CONN1.2 4.5,5.26 4.75,5.51 4.75,7.29 L3.2 4.75,8.71 4.75,9.39 4.24,9.9 C12.1 4.7,10.37 4.7,10.6 4.24,11.06 R5.2 4.24,11.08 4.69,11.53 4.69,12.39 5.63,13.34 8,13.34 v3(8.51,13.84)
  BOTTOM w0.102: v3(8.51,13.84) 9.02,13.34 9.2,13.34 10.92,15.06 10.92,27.87 24.28,41.23 24.28,63.34 20.67,66.95 15.77,66.95 15.41,66.6 CONN2.22
USB_DP: length 82.2
  TOP w0.102: CONN1.3 5.15,5.26 4.95,5.46 4.95,7.39 L4.2 4.95,8.61 4.95,9.49 5.36,9.9 C13.2 5.36,9.92 4.9,10.38 4.9,10.6 5.36,11.06 R6.1 5.36,11.08 4.89,11.56 4.89,12.31 5.72,13.13 8.2,13.13 v3(8.51,12.83)
  BOTTOM w0.102: v3(8.51,12.83) 8.81,13.13 9.28,13.13 11.13,14.98 11.13,27.79 24.49,41.15 24.49,63.42 20.75,67.16 15.72,67.16 15.48,67.4 CONN2.24
USB_ILIM: length 3.3
  TOP w0.127: U1.2 v2(7.11,23.47) 7.11,23.13 7.06,23.08 R2.2
  BOTTOM w0.127: v2(7.11,23.47) 7.85,23.47 v1(8.13,23.75)
USB_ILIM_R: length 3.1
  TOP w0.127: v2(6.15,20.73) R4.2 R2.1
  BOTTOM w0.127: v2(6.15,20.73) 6.35,20.53 v1(6.35,19.56)
USB_PWR_FAULT_N: length 60.5
  TOP w0.127: U1.3 7.76,23.38 8.13,23.01 R3.1 8.14,22.55 9.27,23.68 v2(9.27,26.54)
  BOTTOM w0.127: CONN2.31 5,70.6 v1(4.35,69.95) 3.44,69.95 2.49,68.99 2.49,32.05 6.35,28.19 8.89,28.19 9.27,27.81 v2(9.27,26.54)
USB_PWR_ON: length 57.9
  TOP w0.127: U1.4 7.76,27.68 8.38,28.3 R1.1 8.93,28.76 9.12,28.57 9.12,27.91 v2(8.64,27.43)
  BOTTOM w0.127: v2(8.64,27.43) 8.13,27.94 6.22,27.94 2.24,31.93 2.24,69.59 v1(4.49,71.85) 5.43,71.85 5.88,71.4 CONN2.33
USB_VBUS: length 2.1
  TOP w0.508: C8.1 3.79,24.56 3.78,24.56 ; C8.1 5.2,24.56 5.21,24.56 ; C8.1 4.57,23.88
  vias: v1(4.57,22.38) v2(2.62,23.34) v2(3.61,23.39) v2(4.4,23.34) v2(5.48,23.82)
USB_VCC5P0: length 9.4
  TOP w0.508: C6.2 6.4,28.25 6.35,28.19 ; C6.2 5.71,28.7 ; C6.2 v2(6.4,29.67)
  BOTTOM w0.457: CONN2.40 v2(16.34,73.8) ; CONN2.36 v2(16.37,72.2) ; CONN2.38 v2(16.4,73) ; C20.1 v2(17.78,72.96)
  BOTTOM w0.508: C21.1 19.3,59.56
  vias: v1(9.78,36.07) v1(12.32,38.48) v1(17.53,42.8) v1(20.95,47.12) v1(21.72,54.1) v2(4.95,30.73) v2(5.71,30.73) v2(5.71,29.97) v2(6.48,30.73) v2(19.74,60.12) v2(19.79,58.34) v2(20.83,60.15) v2(20.78,58.39) v2(21.89,60.15) v2(21.89,58.32)
VSTB_3V3: length 51.1
  TOP w0.508: 8.38,30.23 R1.2 9.09,29.66 ; 8.13,21.08 R3.2 9.09,21.64
  TOP w0.762: v2(24.77,3.42) 24.77,2.95 24.5,2.67 LED2.A ; LED1.A 16.53,2.67 18.05,2.67 v2(18.16,2.55) 18.16,3.66 18.08,3.74 18.08,10.49 17.78,10.79 v2(17.78,11.3)
  BOTTOM w0.457: CONN2.2 16.88,58.6 16.93,58.55 C22.2 ; CONN2.4 16.76,59.4 16.93,59.56 C21.2
  BOTTOM w0.508: 17.53,60.07 17.58,60.02 C21.2 C22.2 17.58,57.97 17.53,57.91
  BOTTOM w0.762: v2(24.77,3.42) 25.11,3.76 v1(25.11,9.43) 23.37,11.18 21.72,11.18 ; v2(18.16,2.55) 19.08,2.55 19.27,2.36 19.44,2.36 19.62,2.18 20.37,2.18 20.92,1.63 LED4.A ; LED3.A 11.86,2.27 11.28,2.27 10.47,3.08 v1(10.47,7.66) 10.47,8.69 12.7,10.92 13.21,10.92
  vias: v1(13.97,34.04) v1(15.24,11.68) v1(19.68,11.56) v2(9.78,30.35) v2(10.29,29.72) v2(16.26,36.45) v2(16.26,35.43) v2(16.51,56.64) v2(16.51,55.75) v2(16.51,11.43) v2(17.53,56.64) v2(17.53,55.75)
N24947217: length 13.7
  TOP w0.508: C2.2 9.48,97.41 8.89,98 H1.3 ; H1.5 5,94.11 4.14,93.25 v2(4.14,91.03) C4.2
  BOTTOM w0.254: v2(4.14,91.03) v1(4.14,88.87)
N24947278: length 12.9
  TOP w0.508: C9.2 v2(31.57,26.19) 31.57,28.54 31,29.11 H3.5 ; C5.2 30.38,40.47 31,39.85 H3.1
  BOTTOM w0.254: v2(31.57,26.19) 31.57,25.16 v1(31.21,24.8)
N24947339: length 12
  TOP w0.508: C3.2 v2(30.61,91.82) 30.61,93.72 31,94.11 H2.5 ; H2.8 28.94,99.66 27.34,99.66 27.24,99.57 C1.2
  BOTTOM w0.254: v2(30.61,91.82) 30.61,89.92 v1(31.11,89.41)

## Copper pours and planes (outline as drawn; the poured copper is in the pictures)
GND on TOP: 16.26,1.02 16.26,1.49 16.8,2.03 17.8,2.03 18.45,1.99 18.8,2.55 18.8,3.83 18.84,3.91 18.92,3.93 19.01,3.91 19.1,3.91 19.13,3.92 19.3,3.75 20.19,3.75 21.19,2.75 21.19,2.52 21.06,2.39 20.74,2.39 20.74,1.19 20.57,1.02
GND on TOP: outline of 328 points within 1.02,1.02 33.98,101.98
GND on TOP: 20.83,5.35 20.87,4.81 21.36,4.58 21.38,4.58 22.28,3.68 22.28,3.38 22.06,3.16 21.68,3.16 20.45,4.38 19.68,4.38 19.61,4.41 19.58,4.48 19.52,4.7 19.37,4.87 19.37,5.71 19.58,5.93 20.49,5.93 20.83,5.59
GND on TOP: 8.92,22.88 9.59,23.55 9.59,26.11 9.77,26.73 9.23,27.08 9.13,27.12 9.12,27.22 9.16,27.35 9.17,27.49 9.16,27.51 9.71,28.05 10.2,28.05 10.79,27.45 10.79,23.09 10.05,22.35 9.19,22.35 8.92,22.63
GND on TOP: 14.67,5.74 14.67,5.01 14.04,4.37 14,4.41 13.25,4.37 13.28,3.62 13.28,3.35 13.25,3.32 12.77,3.32 12.13,3.97 12.13,4.27 12.32,4.54 12.31,4.88 12.3,4.91 13.33,5.93 14.48,5.93
GND on TOP: 16.11,3.66 15.99,4.06 15.61,4.26 15.57,4.27 15.56,4.31 15.56,4.44 16.32,5.2 16.32,5.74 16.51,5.93 17.26,5.93 17.37,5.82 17.37,3.48 17.2,3.3 16.41,3.3 16.11,3.61
GND on BOTTOM: outline of 255 points within 1.02,9.59 33.98,101.98
GND on BOTTOM: outline of 86 points within 2.81,31.34 17.91,70.28
GND on G2: 6.01,7.17 6.12,7.01 6.65,6.47 6.65,3.94 6.39,3.68 3.84,3.68 3.63,3.89 3.63,7.11 3.76,7.28 3.81,7.49 3.81,8.51 3.76,8.72 3.63,8.89 3.18,9.35 3.01,9.48 2.79,9.53 1.4,9.53 1.02,9.91 1.02,101.98 33.98,101.98 33.98,12.48 33.8,12.29 27.02,12.29 26.83,12.25 26.66,12.14 25.7,11.18 25.57,11.01 25.53,10.79 25.53,1.02 10.06,1.02 10.06,8.51 10.01,8.72 9.88,8.89 9.33,9.45 9.15,9.58 8.94,9.63 6.93,9.63 6.74,9.59 6.58,9.48 6.12,9.03 6.01,8.86 5.97,8.67 ; 9 cut-outs
GND on V3: 6.01,7.17 6.12,7.01 6.65,6.47 6.65,3.94 6.39,3.68 3.84,3.68 3.63,3.89 3.63,7.11 3.76,7.28 3.81,7.49 3.81,8.51 3.76,8.72 3.63,8.89 3.18,9.35 3.01,9.48 2.79,9.53 1.4,9.53 1.02,9.91 1.02,101.98 33.98,101.98 33.98,12.48 33.8,12.29 27.02,12.29 26.83,12.25 26.66,12.14 25.7,11.18 25.57,11.01 25.53,10.79 25.53,1.02 10.06,1.02 10.06,8.51 10.01,8.72 9.88,8.89 9.33,9.45 9.15,9.58 8.94,9.63 6.93,9.63 6.74,9.59 6.58,9.48 6.12,9.03 6.01,8.86 5.97,8.67 ; 8 cut-outs
GND_USB on BOTTOM: 5.03,11.38 5.71,11.38 5.97,11.13 5.97,6.99 6.4,6.55 6.4,5.89 6.22,5.71 5.33,5.71 4.9,6.15 4.9,11.25
VBUS_5V on TOP: 4.06,13.34 2.99,13.34 2.88,13.44 2.88,13.89 2.82,13.95 2.09,13.95 1.85,14.19 1.85,21.1 1.97,21.22 2.57,21.22 2.61,21.19 3.45,21.19 3.5,21.24 5.05,21.24 5.06,21.23 5.26,21.23 5.42,21.07 5.42,14.69
VBUS_5V on BOTTOM: 3.95,12.35 4.57,11.73 4.57,5.84 4.45,5.71 3.94,5.71 3.63,6.02 3.63,9.07 3.61,9.09 3,9.71 3,11.08 2.72,11.37 2.3,11.37 2.03,11.64 2.03,12.68 1.83,12.87 1.83,21.54 1.91,21.62 4.93,21.62 5.16,21.39 5.16,15.24 3.95,14.03
CHASSIS on TOP, G2, V3: 2.62,3.68 2.65,3.49 2.76,3.32 3.27,2.81 3.44,2.7 3.63,2.67 6.6,2.67 6.8,2.71 6.96,2.81 7.52,3.37 7.63,3.54 7.67,3.73 7.67,6.68 7.62,6.89 7.49,7.07 6.99,7.57 6.99,8.46 7.14,8.61 8.73,8.61 9.04,8.3 9.04,1.02 1.02,1.02 1.02,8.2 1.33,8.51 2.58,8.51 2.79,8.3 2.79,7.73 2.66,7.55 2.62,7.34
CHASSIS on BOTTOM: 2.62,3.68 2.65,3.49 2.76,3.32 3.27,2.81 3.44,2.7 3.63,2.67 6.6,2.67 6.8,2.71 6.96,2.81 7.52,3.37 7.63,3.54 7.67,3.73 7.67,6.68 7.62,6.89 7.49,7.07 7.12,7.44 6.83,7.44 6.68,7.59 6.68,8.46 6.83,8.61 8.73,8.61 9.04,8.3 9.04,1.02 1.02,1.02 1.02,8.2 1.33,8.51 2.82,8.51 2.92,8.41 2.92,7.59 2.62,7.29
CHASSIS_1 on TOP: 26.54,1.02 26.54,10.59 27.23,11.28 29.35,11.28 29.53,11.1 29.53,9.63 29.42,9.52 29.42,5.39 30.5,2.06 31.58,5.39 31.58,8.63 31.69,8.73 31.69,11.19 31.78,11.28 33.6,11.28 33.96,10.92 33.98,10.9 33.98,7.36 33.92,7.26 33.81,7.28 31.9,6.44 33.81,5.6 33.92,5.62 33.98,5.52 33.98,2.28 33.92,2.18 33.81,2.2 32.48,2.36 31.92,1.14 31.9,1.05 31.82,1.02 29.18,1.02 29.1,1.05 29.08,1.14 27.96,2.5 26.84,1.14 26.82,1.05 26.74,1.02
CHASSIS_1 on BOTTOM, G2, V3: 33.98,1.02 26.54,1.02 26.54,10.59 27.23,11.28 33.6,11.28 33.96,10.92 33.98,10.9
USB_VBUS on TOP: 1.91,25.27 3.84,25.27 4.01,25.1 4.01,24.18 4.19,24 4.95,24 5.13,24.18 5.13,24.99 5.25,25.11 5.88,25.11 5.94,25.05 6.59,25.05 6.6,25.04 6.6,23.55 6.35,23.29 5.66,23.29 5.38,23.01 5.38,21.95 5.24,21.8 1.89,21.8 1.78,21.91 1.78,25.15
USB_VBUS on BOTTOM: 6.05,25.17 6.6,24.61 6.6,22.28 6.2,21.87 1.98,21.87 1.78,22.07 1.78,25.15 1.8,25.17
USB_VCC5P0 on TOP: 6.6,29.46 6.6,26.67 6.6,26.67 6.6,26.52 6.6,26.52 5.99,26.52 4.32,28.19 4.32,30.86 4.83,31.37 6.65,31.37 6.86,31.17 6.86,29.72
USB_VCC5P0 on TOP: 16.27,74.05 19.93,74.05 21.5,72.48 21.5,67.47 20.29,66.26 20.29,62.72 22.2,60.82 22.2,57.7 21.97,57.47 19.83,57.47 18.09,59.21 18.09,69.6 15.91,71.78 15.91,73.69
USB_VCC5P0 on BOTTOM: 19.43,60.52 22.4,60.52 23.1,59.82 23.1,45.34 8.99,31.23 8.99,30.76 8.83,30.59 6.97,30.59 6.73,30.35 6.73,29.59 6.48,29.34 5.71,29.34 4.51,30.54 4.51,34.18 18.16,47.83 18.16,56.9 19.18,57.91 19.18,60.27
USB_VCC5P0 on BOTTOM: 16.12,74.12 18.17,74.12 18.68,73.62 18.68,72.15 18.07,71.54 16.35,71.54 15.95,71.94 15.95,73.95
VSTB_3V3 on TOP: 9.65,31.11 12.73,28.04 12.73,28.04 12.95,27.81 12.95,21.33 12.19,20.57 8.13,20.57 7.75,20.95 7.75,21.08 7.87,21.21 8.51,21.21 8.64,21.34 8.64,21.97 8.76,22.1 10.16,22.1 11.05,22.99 11.05,27.56 9.44,29.17 9.18,29.17 8.89,29.46 8.89,29.97 8.76,30.1 7.92,30.1 7.87,30.15 7.87,30.94 8.05,31.11
VSTB_3V3 on TOP: 15.49,56.77 15.75,57.02 17.78,57.02 18.44,56.36 18.44,9.53 18.03,9.12 16.21,9.12 15.49,9.83
VSTB_3V3 on BOTTOM: 17.91,55.5 17.65,55.24 16.26,55.24 16,55.5 16,59.82 16.51,60.33 17.65,60.33 17.91,60.07
VSTB_3V3 on BOTTOM: 12.95,10.41 12.7,10.67 12.7,11.11 12.73,11.14 12.73,11.97 12.95,12.19 22.35,12.19 22.99,11.56 22.99,10.79 22.61,10.41
VSTB_3V3 on BOTTOM: 16.95,36.77 16.64,37.08 15.44,37.08 9.3,30.94 9.3,29.82 9.91,29.21 10.41,29.21 16.95,35.75
N24947217 on TOP (solid shape): outline of 228 points within 1.5,94.5 8.5,101.5
N24947217 on BOTTOM (solid shape): outline of 228 points within 1.5,94.5 8.5,101.5
N24947278 on TOP (solid shape): outline of 228 points within 27.5,29.5 34.5,36.5
N24947278 on BOTTOM (solid shape): outline of 228 points within 27.5,29.5 34.5,36.5
N24947339 on TOP (solid shape): outline of 235 points within 27.5,94.5 34.5,101.5
N24947339 on BOTTOM (solid shape): outline of 235 points within 27.5,94.5 34.5,101.5

Small or netless copper shapes (teardrops, artwork), in the pictures only: 2 on TOP

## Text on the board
User.Comments: STB V2
Ref Des/Silkscreen Top: P/N:142000002097A REV:0A
DIMENSION: 103 | 98 | 6.44 | 4.2 | 33 | 1 | 3.858 | 4.055 | .039 | .165 | 1.299 | .254 | 56.13 | 2.210 | 0 | .124 | 3.15 | .197 | 5 | .551 | 14 | .563 | 14.3 | .906 | 23 | 1.101 | 27.96 | 1.220 | 31 | 1.378 | 35
PAGE_OUTLINE: CHASSIS | GND | CHASSIS_1
DISPLAY_TOP: CHASSIS | GND | CHASSIS_1
TITLE_DATA_TOP: TOP (COMPONENT_SIDE)                 1
User.5: G2  (GND_LAYER_2)                    2
User.6: V3  (VCC_LAYER_3)                    3
User.7: BOT (SOLDER_SIDE)                    4
User.8: SST (SILKSCREEN_TOP)                 5
User.9: SSB (SILKSCREEN_BOTTOM)              6
User.10: SMT (SOLDER_MASK_TOP)                7
User.11: SMB (SOLDER_MASK_BOTTOM)              8
User.12: DRILL(FINISH HOLE SIZE LIST)          9
User.13: PMT (PASTE_MASK_TOP)                10
User.14: PMB (PASTE_MASK_BOTTOM)             11
User.15: DIM (BOARD_DIMENSION)               12
User.17: FIGURE | SIZE | 10.0 | 12.0 | 43.0 | 60.0 | 28.0 | 40.0 | 118.0 | 125.0 | 138.0 | 52.0x20.0 | TOLERANCE | +3.0/-3.0 | +2.0/-2.0 | +3.0/-0.0 | ALL UNITS ARE IN MILS | PLATED | NON-PLATED | QTY | 4 | 337 | 1 | 2 | 3 | DRILL CHART: TOP to BOTTOM
User.20: Excess check:Aug 07 10:56:00 2018 | PadStack_Check:Aug 08 10:41:44 2018 | XY-Check acute:Aug 08 10:45:19 2018 | XY-Check cline width:Aug 08 10:45:48 2018 | XY-Check rotation:Aug 08 13:58:19 2018 | XY-Check txt overlap:Aug 08 13:57:51 2018 | XY-Check txt:Aug 08 10:47:26 2018 | XY-Create nettxt:Jul 31 14:10:00 2018 | XY-Create plane:Aug 01 14:02:33 2018 | XY-Dxf to pin check:Aug 08 10:43:34 2018 | XY-Etch cross-TOP-G2:Aug 08 10:45:32 2018 | XY-Etch cross-V3-BOTTOM:Aug 08 10:45:32 2018 | XY-Excess check:Aug 07 10:56:00 2018 | XY-Mask check:Aug 08 10:46:23 2018 | XY-Norefdes:Aug 08 13:58:08 2018 | XY-PadStack_Check:Aug 08 10:41:44 2018 | XY-Plane net check:Aug 08 10:44:55 2018 | XY-Prop check:Aug 08 10:45:28 2018 | XY-Symbol cross:Aug 07 10:56:44 2018 | XY-shape pin check:Aug 08 10:48:29 2018 | XY-via check:Aug 08 10:48:17 2018 | check acute:Aug 08 10:45:19 2018 | check cline width:Aug 08 10:45:48 2018 | check rotation:Aug 08 13:58:19 2018 | check txt overlap:Aug 08 13:57:51 2018 | check txt:Aug 08 10:47:26 2018 | create nettxt:Jul 31 14:10:00 2018 | create plane:Aug 01 14:02:33 2018 | dxf to pin check:Aug 08 10:43:34 2018 | etch cross-TOP-G2:Aug 08 10:45:32 2018 | etch cross-V3-BOTTOM:Aug 08 10:45:32 2018 | norefdes:Aug 08 13:58:08 2018 | plane net check:Aug 08 10:44:55 2018 | prop check:Aug 08 10:45:28 2018 | shape pin check:Aug 08 10:48:29 2018 | symbol cross:Aug 07 10:56:43 2018 | via check:Aug 08 10:48:17 2018
